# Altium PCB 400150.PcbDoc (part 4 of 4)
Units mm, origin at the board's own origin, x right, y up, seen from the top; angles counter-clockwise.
Board outline 101.6 x 63.5 mm, 4 copper layers (Top Layer, Mid-Layer 1, Mid-Layer 2, Bottom Layer), stack 1.582 mm thick; 248 components, 179 nets, 1093 pads, 875 vias.
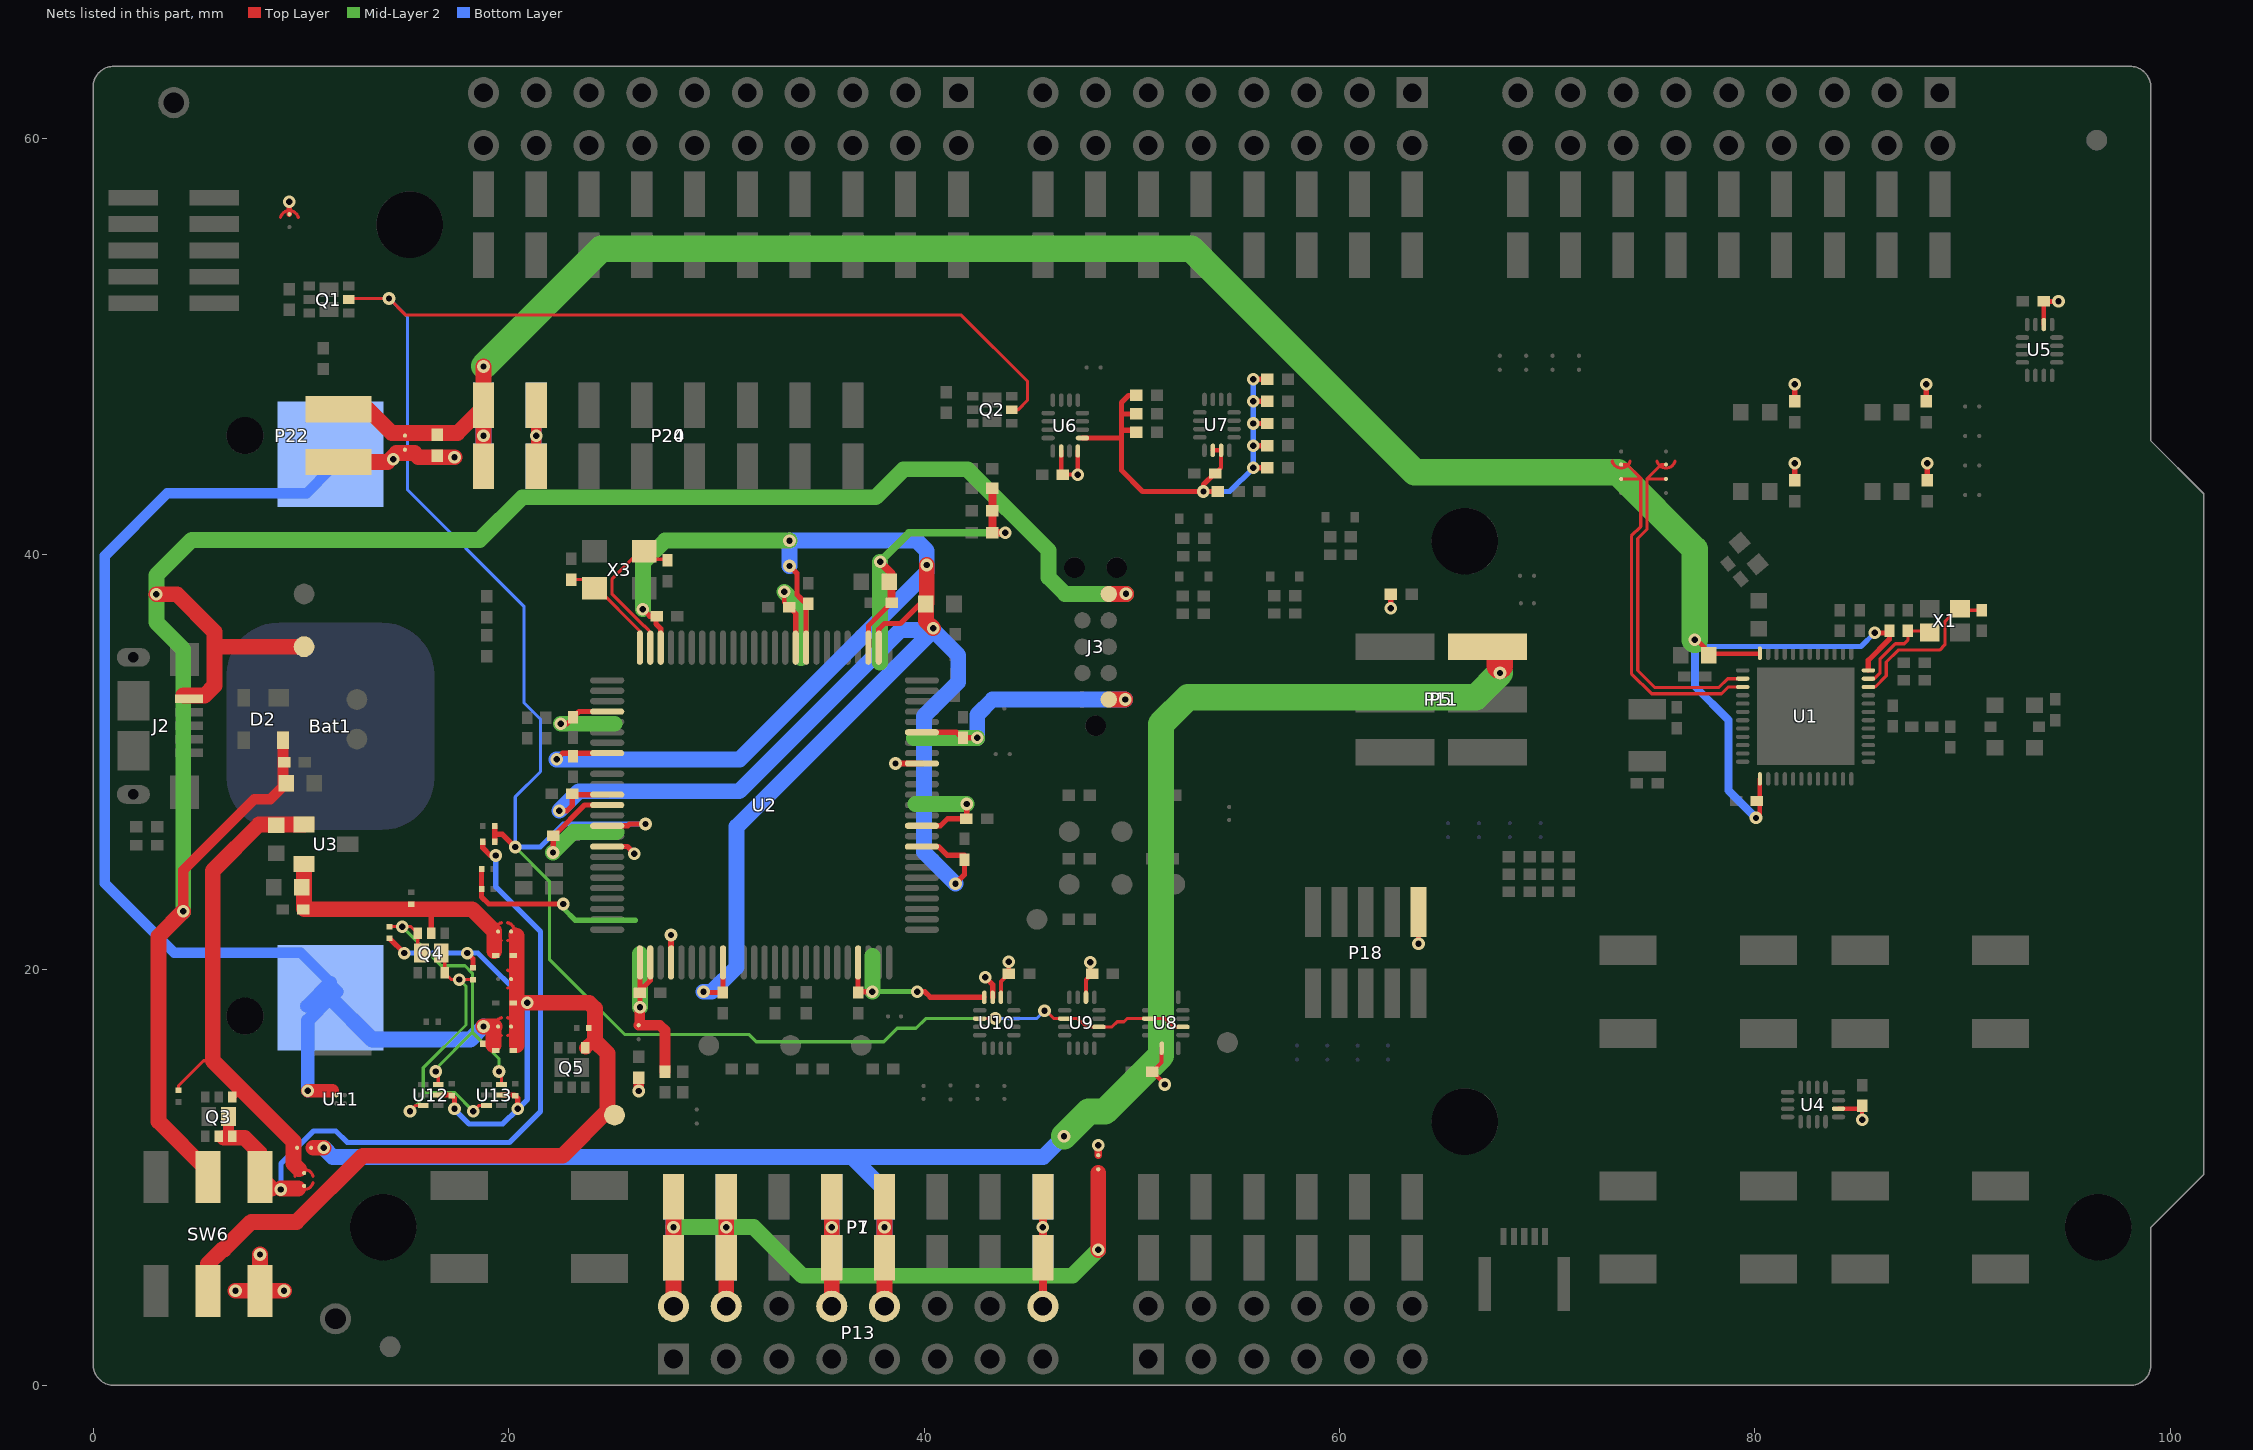
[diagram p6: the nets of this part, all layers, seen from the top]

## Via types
v1: diameter 0.61, hole 0.305, Top Layer to Bottom Layer, tented both sides, 836 vias
v2: diameter 0.61, hole 0.305, Top Layer to Bottom Layer, 23 vias
v3: diameter 0.66, hole 0.33, Top Layer to Bottom Layer, tented both sides, 16 vias

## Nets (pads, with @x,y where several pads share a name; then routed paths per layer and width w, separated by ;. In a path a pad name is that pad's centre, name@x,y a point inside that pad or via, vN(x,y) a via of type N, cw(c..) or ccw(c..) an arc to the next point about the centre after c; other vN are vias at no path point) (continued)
USB_DETECT: Q1.2 Q2.2 R44.2 R45.1 U2.90 U8.2 U8.10 U9.2 U9.10 U10.2 | length 117
  Top Layer w0.152: Q1.2@12.299,52.263 12.35,52.314 v1(14.249,52.314) 15.052,51.511 41.798,51.511 44.983,48.326 44.983,47.408 44.53,46.954 Q2.2@44.232,46.954 ; U10.2@42.679,17.65 v1(43.431,17.65) ; v1(45.796,18.034) 45.872,18.034 46.257,17.65 U9.2@46.771,17.65 47.396,17.65 47.796,17.25 U9.10@48.421,17.25 49.051,17.25 49.301,17.501 49.624,17.501 49.773,17.65 U8.10@50.813,17.65 51.616,17.65 52.016,17.25 U8.2@52.463,17.25
  Top Layer w0.254: R44.2@19.335,26.162 19.335,26.518 ; R45.1@19.335,26.924 19.335,26.518 ; v1(20.32,25.908) 19.71,26.518 19.335,26.518 ; U2.90@24.749,26.93 25.733,26.93 25.818,27.015 v1(26.594,27.015)
  Mid-Layer 2 w0.152: v1(20.32,25.908) 21.965,24.263 21.965,20.507 25.58,16.891 31.572,16.891 31.928,16.535 38.063,16.535 38.709,17.181 39.612,17.181 40.081,17.65 v1(43.431,17.65)
  Bottom Layer w0.152: v1(14.249,52.314) 15.137,51.426 15.137,43.104 20.738,37.503 20.738,32.864 21.539,32.063 21.539,29.54 20.32,28.321 v1(20.32,25.908) ; v1(43.431,17.65) 45.412,17.65 v1(45.796,18.034)
  Bottom Layer w0.254: v1(20.32,25.908) 21.524,25.908 22.631,27.015 v1(26.594,27.015)
V5V: P1.5 P5.2 P7.5 P11.2 P13.10 SB34.1 | length 89.5
  Top Layer w0.762: 10.617,11.43 v1(11.1,11.43) ; P13.10@38.1,3.8 P1.5@38.1,6.145 v1(38.1,7.61) P1.5@38.1,9.075 ; P5.2@67.12,35.55 P5.2@67.722,34.947
  Top Layer w1.27: 67.722,34.628 P5.2@67.722,34.947
  Mid-Layer 2 w1.27: v1(46.736,11.984) 47.928,13.176 48.711,13.176 49.505,13.97 51.41,15.875 51.41,31.826 52.705,33.122 66.558,33.122 v1(67.722,34.285)
  Bottom Layer w0.762: v1(11.1,11.43) 11.542,10.988 36.517,10.988 ; P7.5@38.1,6.145 v1(38.1,7.61) 38.1,9.405 36.517,10.988 ; v1(46.736,11.984) 45.74,10.988 36.517,10.988 ; v1(67.722,34.285) P11.2@67.722,35.55
VBAT: Bat1.1 D8.2 R49.1 SB11.2 U11.A1 | length 63.8
  Top Layer w0.254: R49.1@18.751,16.434 19.228,16.434 19.279,16.383 ; v1@18.751,17.227 v1(18.796,17.272)
  Top Layer w0.635: v1(10.338,14.173) 11.532,14.173
  Top Layer w0.762: v1(18.796,17.272) 19.325,17.272 19.279,17.225 19.279,16.383
  Bottom Layer w0.508: Bat1.1@10,20.818 11.428,19.39 Bat1.1@10,20.818 ; Bat1.1@10,20.818 3.912,20.818 0.559,24.171 0.559,39.919 3.581,42.941 Bat1.1@10.279,42.941 ; Bat1.1@10.279,42.941 11.428,44.09 Bat1.1@10.279,42.941
  Bottom Layer w0.635: Bat1.1@10.287,18.249 Bat1.1@11.428,19.39 ; v1(10.338,14.173) 10.338,17.551 Bat1.1@11.43,18.644 ; Bat1.1@11.73,18.943 Bat1.1@11.428,19.245 ; Bat1.1@11.428,19.245 Bat1.1@11.428,19.39 ; Bat1.1@11.428,19.245 Bat1.1@11.428,19.39
  Bottom Layer w0.762: Bat1.1@11.43,18.644 13.437,16.637 18.161,16.637 v1(18.796,17.272)
VBUS: C20.2 C21.2 D2.4 J2.1 J3.5 SW6.5 TP3.1 | length 106.8
  Top Layer w0.508: v1(4.343,22.809) 4.343,24.79 7.762,28.209 8.535,28.209 C20.2@9.297,28.971 ; C20.2@9.144,28.895 D2.4@9.144,31.045
  Top Layer w0.762: v1(3.048,38.075) 4.039,38.075 5.842,36.271 5.842,33.674 5.366,33.198 J2.1@4.343,33.198 ; v1(4.343,22.809) 3.15,21.615 3.15,12.7 5.537,10.312 SW6.5@5.537,10.03 ; 5.878,35.55 TP3.1@10.16,35.55 ; J3.5@48.895,38.09 v1@49.723,38.09
  Mid-Layer 2 w0.762: v1(4.343,22.809) 4.343,35.43 3.048,36.726 v1(3.048,38.075) 3.048,38.989 4.754,40.695 18.618,40.695 20.671,42.748 37.672,42.748 39.018,44.094 42.087,44.094 45.998,40.183 45.998,38.879 46.783,38.093 v1(49.723,38.093)
VBUS': Q3.2 Q3.3 R44.1 SB33.2 SW6.6 | length 35.4
  Top Layer w0.254: R44.1@18.765,26.162 18.765,25.857 19.121,25.502 v1(19.38,25.502)
  Top Layer w0.508: Q3.3@6.52,12.929 6.52,12.159 Q3.3@6.695,11.984
  Top Layer w0.762: 6.299,11.913 7.29,11.913 8.026,11.176 8.026,10.088 SW6.6@7.968,10.03 ; SW6.6@8.037,10.03 SW6.6@8.604,9.463 ; v1@9.042,9.463 9.877,9.463
  Bottom Layer w0.254: v1(9.042,9.423) 9.042,10.668 10.617,12.243 11.684,12.243 12.243,11.684 20.041,11.684 21.539,13.183 21.539,21.844 19.38,24.003 v1(19.38,25.502)
VCORE: C25.2 C27.2 C31.2 C34.2 C36.1 C39.2 C40.2 U2.9 U2.34 U2.52 U2.59 U2.73 U2.83 U2.87 | length 123.2
  Top Layer w0.254: v1(22.317,30.128) 22.608,30.419 U2.83@24.738,30.419 ; v1(22.444,27.65) 22.802,27.65 23.071,27.919 C40.2@23.071,28.489 ; C40.2@23.24,28.43 U2.87@24.749,28.43 ; v1(26.467,37.353) 26.797,37.023 C36.1@27.101,37.023 ; C36.1@27.125,37.023 C36.1@27.101,37.023 ; U2.73@27.324,35.505 27.324,36.42 27.101,36.643 C36.1@27.101,37.023 ; v1(29.388,18.938) 29.421,18.905 C25.2@30.318,18.905 ; C25.2@30.324,18.93 U2.9@30.324,20.355 ; v1(33.528,39.436) 33.807,39.157 33.884,39.08 33.884,38.055 34.036,37.903 C34.2@34.378,37.561 ; U2.59@34.324,35.505 34.324,37.507 C34.2@34.378,37.561 ; C34.2@34.432,37.615 C34.2@34.378,37.561 ; U2.52@37.824,35.505 37.824,36.391 38.101,36.667 38.862,36.667 39.802,37.607 C31.2@40.092,37.607 ; U2.34@39.899,25.93 40.7,25.93 41.113,25.517 C27.2@41.908,25.517 ; v1(41.519,24.145) 41.951,24.577 C27.2@41.951,25.296 ; C27.2@41.933,25.356 C27.2@41.933,25.517
  Top Layer w0.762: v1(40.132,39.487) 40.132,37.647 C31.2@40.092,37.607 40.092,36.784 v1(40.437,36.439)
  Mid-Layer 2 w0.762: v1(26.467,37.353) 26.467,39.588 27.534,40.655 v1(33.528,40.655)
  Bottom Layer w0.762: v1(22.317,30.128) 31.128,30.128 40.132,39.131 v1(40.132,39.487) 40.132,40.173 39.649,40.655 v1(33.528,40.655) v1(33.528,39.436) ; v1(22.444,27.65) 23.383,28.59 31.105,28.59 38.862,36.347 v1@40.437,36.347 ; v1(29.388,18.938) 29.784,18.938 30.978,20.132 30.978,26.888 v1@40.437,36.347 ; v1(41.519,24.145) 39.995,25.669 39.995,32.201 41.646,33.852 41.646,35.138 v1@40.437,36.347
VDD: C14.2 C44.2 C45.2 C46.2 C54.2 C55.2 P18.1 P20.2 P22.2 P24.2 R1.2 R2.2 R3.2 R4.2 R6.1 R39.2 R57.2 SB9.2 SB32.1 SB35.2 SW6.3 U4.14 U5.14 U6.14 U6.16 U8.14 U9.14 U10.14 U10.15 | length 36.8
  Top Layer w0.203: U10.14@43.704,18.675 43.704,19.439 C55.2@44.077,19.812 v1(44.077,20.388) ; C46.2@46.526,43.951 46.638,43.839 C46.2@46.642,43.835 ; C46.2@46.603,43.917 U6.14@46.603,44.972 ; C46.2@46.685,43.835 v1(47.396,43.835) ; v1@47.403,43.835 U6.16@47.403,44.972 ; U9.14@47.796,18.675 47.796,19.518 C54.2@48.09,19.812 48.006,19.896 v1(48.006,20.359) ; U8.14@51.438,16.225 51.438,15.531 C14.2@50.995,15.088 51.587,14.495 v1(51.587,14.478) ; U4.14@84.02,13.313 85.153,13.313 C44.2@85.158,13.318 ; v1(85.158,12.776) C44.2@85.158,13.318 ; C44.2@85.158,13.445 C44.2@85.158,13.318 ; C45.2@93.896,52.172 93.901,52.167 U5.14@93.901,51.06
  Top Layer w0.254: SB32.1@9.449,56.37 9.449,56.545 v1(9.449,56.972) ; v1(42.951,19.634) 43.304,19.282 U10.15@43.304,18.675 ; v1(62.467,37.397) R39.2@62.467,38.075 ; v1(63.805,21.26) P18.1@63.805,22.772 ; R3.2@81.915,43.553 v1(81.915,44.374) ; R1.2@81.915,47.363 v1(81.915,48.192) ; R2.2@88.24,47.363 v1(88.24,48.184) ; R4.2@88.291,43.553 v1(88.291,44.374) ; C45.2@93.896,52.172 v1(94.607,52.172)
  Top Layer w0.381: SB35.2@48.387,11.072 v1(48.387,11.557)
  Top Layer w0.508: P20.2@21.336,44.245 v1(21.336,45.71) P20.2@21.336,47.175 ; v1(26.266,14.165) R57.2@26.266,14.806
  Top Layer w0.762: v1(6.858,4.548) v1(9.195,4.548) ; SW6.3@8.037,4.479 v1(8.037,6.29) ; P22.2@11.811,44.44 14.173,44.44 14.605,44.872 15.469,44.872 15.672,44.668 v1(17.399,44.668)
  Bottom Layer w0.508: P24.2@21.336,44.245 v1(21.336,45.71) P24.2@21.336,47.175
  other v1: 14.453,44.567
VDD_NRF: C5.1 C8.1 C9.1 P20.1 P22.1 P24.1 R6.2 SB9.1 U1.13 U1.36 U1.48 | length 114
  Top Layer w0.229: v1(77.105,35.888) 77.188,35.888 77.78,35.296 77.865,35.211 U1.48@80.225,35.211 ; v1(80.047,27.309) 80.235,27.497 U1.13@80.235,29.186
  Top Layer w0.254: U1.36@85.457,34.439 85.457,34.899 86.473,35.915 C8.1@86.473,36.207 ; v1(85.762,36.225) 85.779,36.207 C8.1@86.473,36.207 ; C8.1@86.473,36.309 C8.1@86.473,36.207
  Top Layer w0.381: C9.1@77.78,35.126 C9.1@77.78,35.296
  Top Layer w0.762: P22.1@11.811,46.98 13.233,46.98 14.376,45.837 17.547,45.837 18.796,47.086 v1(18.796,45.71) P20.1@18.796,44.245 ; P20.1@18.796,47.175 v1(18.796,49.037)
  Mid-Layer 2 w1.27: v1@18.821,49.063 24.47,54.712 52.857,54.712 63.627,43.942 73.406,43.942 77.105,40.243 v1(77.105,35.888)
  Bottom Layer w0.254: v1(77.105,35.888) 77.429,35.564 85.101,35.564 v1(85.762,36.225)
  Bottom Layer w0.381: v1(77.105,35.888) 77.105,33.65 78.728,32.027 78.728,28.629 v1(80.047,27.309)
  Bottom Layer w0.762: P24.1@18.796,44.245 v1(18.796,45.71) P24.1@18.796,47.175
VDD_SAM: C24.2 C26.2 C28.2 C29.2 C32.2 C33.2 C35.2 C38.2 C41.2 J3.1 R5.2 R19.2 R20.2 R21.2 R22.2 R23.2 SB29.2 U2.1 U2.2 U2.4 U2.22 U2.36 U2.42 U2.45 U2.53 U2.60 U2.79 U2.88 U2.92 U10.16 | length 91.5
  Top Layer w0.152: U2.88@24.749,27.93 U2.88@24.917,27.93
  Top Layer w0.203: v1(33.274,38.2) 33.274,37.691 C35.2@33.51,37.455
  Top Layer w0.254: R20.2@18.704,24.844 R19.2@18.704,23.893 18.704,23.511 19.05,23.165 v1(22.631,23.165) ; v1@22.147,25.644 C41.2@22.147,26.457 ; C41.2@22.223,26.49 23.663,27.93 U2.88@24.749,27.93 ; v1(22.52,31.841) 22.807,31.841 C38.2@23.104,32.138 ; C38.2@23.112,32.146 23.396,32.43 U2.79@24.749,32.43 ; U2.92@24.749,25.93 25.721,25.93 v1(26.059,25.592) ; U2.1@26.324,20.355 26.324,18.887 26.326,18.886 v1(26.326,18.196) ; C24.2@26.33,18.989 26.824,19.483 U2.2@26.824,20.355 ; C35.2@33.51,37.455 33.824,37.141 U2.60@33.824,35.505 ; C26.2@36.824,19.104 U2.22@36.824,20.355 ; C26.2@36.863,18.938 v1(37.516,18.938) ; U2.53@37.324,35.505 37.324,36.562 37.587,36.825 38.333,37.571 C32.2@38.333,37.658 ; v1(39.675,18.948) 40.03,18.948 40.304,18.675 U10.16@42.875,18.675 ; U2.36@39.899,26.93 40.798,26.93 41.138,27.269 C28.2@42.035,27.269 42.052,27.287 v1(42.052,27.981) ; U2.42@39.899,29.93 U2.42@39.918,29.911 ; U2.45@39.899,31.43 41.55,31.43 C29.2@41.74,31.24 ; C29.2@41.875,31.164 v1(42.56,31.164)
  Top Layer w0.305: U2.4@27.824,20.355 v1(27.824,21.676) ; v1(38.629,29.93) U2.42@39.899,29.93
  Top Layer w0.381: v1(37.887,39.639) 38.438,39.088 C32.2@38.438,37.658 ; R23.2@43.295,43.17 R22.2@43.295,42.103 R21.2@43.295,41.036 v1(43.906,41.036)
  Top Layer w0.508: v1(26.326,18.196) 26.326,17.39 SB29.2@26.266,17.33 27.287,17.33 27.532,17.085 R5.2@27.532,15.101
  Top Layer w0.762: J3.1@48.895,33.01 v1(49.682,33.01)
  Mid-Layer 2 w0.254: v1(22.631,23.165) 22.631,22.963 23.217,22.377 26.111,22.377 ; v1@37.526,18.948 v1(39.675,18.948)
  Mid-Layer 2 w0.381: v1(37.887,39.639) 39.284,41.036 v1(43.906,41.036)
  Mid-Layer 2 w0.508: v1(37.516,18.938) v1@37.526,18.948
  Mid-Layer 2 w0.762: v1(22.139,25.644) 23.123,26.628 25.193,26.628 ; v1(22.52,31.841) 25.116,31.841 ; v1(26.326,18.196) 26.326,20.76 ; v1(33.274,38.2) 34.083,37.391 34.083,35.01 ; v1(37.516,18.938) 37.516,20.659 ; 37.887,34.781 v1(37.887,39.639) ; 39.518,31.164 v1(42.56,31.164) ; 39.594,27.981 v1(42.052,27.981)
  Bottom Layer w0.762: v1(42.56,31.164) 42.56,32.273 43.297,33.01 v1(49.682,33.01)
VEXT: C47.2 R29.2 R30.2 R31.2 R32.2 R33.2 R34.2 R35.2 R36.2 R37.2 U6.1 U7.14 U7.15 | length 25.8
  Top Layer w0.203: U7.14@53.9,45.003 U7.15@54.3,45.003 54.3,44.168 C47.2@54.018,43.885
  Top Layer w0.254: U6.1@47.628,45.597 49.503,45.597 ; R29.2@50.214,45.867 50.113,45.968 49.581,45.968 49.503,46.046 ; R30.2@50.214,46.756 49.503,46.756 ; R31.2@50.214,47.645 49.839,47.645 49.503,47.308 49.503,46.756 ; C47.2@54,43.903 53.449,43.352 v1(53.449,43.022) ; R37.2@54.143,43.022 v1(53.449,43.022) ; v1(55.853,44.161) R32.2@56.521,44.161 ; v1(55.853,45.228) R33.2@56.521,45.228 ; v1(55.853,46.295) R34.2@56.521,46.295 ; v1(55.853,47.361) R35.2@56.521,47.361 ; v1(55.853,48.428) R36.2@56.521,48.428 ; 49.503,45.597 49.503,46.046 ; 49.503,45.597 49.503,44.044 50.525,43.022 v1(53.449,43.022) ; 49.503,46.046 49.503,46.756
  Bottom Layer w0.254: v1(53.449,43.022) 54.714,43.022 v1(55.853,44.161) v1(55.853,45.228) v1(55.853,46.295) v1(55.853,47.361) v1(55.853,48.428)
VEXT_DETECT: Q4.3 R47.2 U12.6 U13.6 | length 16.1
  Top Layer w0.152: R47.2@14.275,22.078 v1(14.884,22.078) 15.306,22.078 Q4.3@15.631,21.753 ; Q4.3@15.631,21.748 15.631,20.978 Q4.3@15.806,20.803 ; v1(16.492,15.105) 16.619,14.978 U12.6@16.619,14.47 ; v1(19.54,15.105) 19.667,14.978 U13.6@19.667,14.47
  Mid-Layer 2 w0.152: v1(14.884,22.078) 16.77,20.193 17.907,20.193 18.263,19.837 18.263,16.993 ; v1(16.492,15.105) 16.492,15.222 18.263,16.993 ; v1(19.54,15.105) 19.54,15.716 18.263,16.993
VIN: P1.8 P7.8 P13.16 | length 8.2
  Top Layer w0.381: P13.16@45.72,3.8 P1.8@45.72,6.145 v1(45.72,7.61) P1.8@45.72,9.075
  Bottom Layer w0.381: P7.8@45.72,6.145 v1(45.72,7.61) P7.8@45.72,9.075
VIO: P1.1 P1.2 P1.4 P7.1 P7.2 P7.4 P13.2 P13.4 P13.8 SB35.1 | length 54
  Top Layer w0.381: v1(35.56,7.61) P1.4@35.56,9.075
  Top Layer w0.762: P13.2@27.94,3.8 P1.1@27.94,6.145 P1.1@27.94,9.075 ; P13.4@30.48,3.8 v1(30.48,7.61) P1.2@30.48,9.075 ; P13.8@35.56,3.8 P1.4@35.56,9.075 ; v1(48.387,6.518) 48.387,10.226
  Mid-Layer 2 w0.762: v1(27.94,7.61) v1(30.48,7.61) 31.801,7.61 34.138,5.273 35.535,5.273 47.142,5.273 v1(48.387,6.518) ; 35.56,5.298 v1(35.56,7.61)
  Bottom Layer w0.762: P7.1@27.94,6.145 P7.1@27.94,9.075 ; P7.2@30.48,6.145 P7.2@30.48,9.075 ; P7.4@35.56,6.145 P7.4@35.56,9.075
VREG_DETECT: Q4.6 R46.2 U12.3 U13.3 | length 14.4
  Top Layer w0.152: v1(15.258,13.191) 15.538,13.47 U12.3@15.893,13.47 ; Q4.6@16.756,20.803 16.931,20.628 Q4.6@16.931,19.858 ; Q4.6@16.931,19.853 17.257,19.527 v1(17.628,19.527) R46.2@18.288,19.527 ; v1(18.306,13.191) 18.586,13.47 U13.3@18.941,13.47
  Mid-Layer 2 w0.152: v1(15.258,13.191) 15.893,13.826 15.893,14.097 ; v1(17.628,19.527) 17.952,19.202 17.952,17.342 15.893,15.283 15.893,14.097 ; v1(18.306,13.191) 17.4,14.097 15.893,14.097
VREG_IN: C16.2 Q3.4 R60.1 SB33.1 SB34.2 U3.1 | length 29.6
  Top Layer w0.152: R60.1@4.115,14.204 4.115,14.419 5.317,15.621 5.766,15.621
  Top Layer w0.381: Q3.4@6.695,13.874 7.087,14.265 7.087,14.3
  Top Layer w0.762: 5.842,24.846 7.986,26.99 ; 9.917,10.397 9.643,10.672 9.643,11.744 7.087,14.3 5.766,15.621 5.766,24.769 7.986,26.99 ; 7.986,26.99 U3.1@10.16,26.99 7.986,26.99
VREG_OUT: C17.2 C18.2 D1.2 Q4.2 R50.1 SB10.2 U3.2 | length 13.9
  Top Layer w0.254: Q4.2@16.281,21.753 16.281,22.901
  Top Layer w0.762: U3.2@10.16,25.09 10.16,22.934 10.178,22.916 16.266,22.916 ; 16.281,22.901 16.266,22.916 ; 19.312,20.891 19.312,21.861 18.257,22.916 16.266,22.916
VSUPPLY: C56.2 C57.2 D1.1 D7.1 D8.1 Q5.4 R46.1 R47.1 R48.1 SB10.1 SB11.1 SB12.1 SW6.2 TP14.1 U12.5 U13.5 | length 58.9
  Top Layer w0.254: R47.1@14.275,21.508 v1(14.98,20.803) ; U12.5@16.619,13.97 17.241,13.97 C56.2@17.272,13.939 17.399,13.812 v1(17.399,13.304) ; v1(18.009,20.803) 18.288,20.523 R46.1@18.288,20.097 ; U13.5@19.667,13.97 20.289,13.97 C57.2@20.32,13.939 20.447,13.812 v1(20.447,13.304)
  Top Layer w0.635: 20.32,21.641 20.32,21.717 ; D7.1@20.396,18.415 v1@20.676,18.415 ; Q5.4@23.718,16.236 24.071,16.589
  Top Layer w0.762: SW6.2@5.537,4.53 5.537,5.842 6.236,6.541 6.297,6.541 7.62,7.864 9.794,7.864 12.979,11.049 22.606,11.049 24.765,13.208 24.765,15.977 24.155,16.586 24.155,18.136 23.876,18.415 v1(20.904,18.415) v1@20.676,18.415 ; 20.396,16.383 20.396,18.415 20.396,21.641
  Bottom Layer w0.254: v1(14.98,20.803) v1(18.009,20.803) 18.517,20.803 v1(20.904,18.415) 20.904,13.761 v1(20.447,13.304) 19.716,12.573 18.098,12.573 v1@17.399,13.272
XC1: C1.1 U1.34 X1.1 | length 8
  Top Layer w0.152: U1.34@85.46,33.611 85.784,33.611 86.318,34.146 86.318,34.814 86.89,35.386 88.886,35.386 89.14,35.64 89.14,36.758 89.691,37.309 C1.1@90.918,37.309
XC2: C2.1 U1.35 X1.3 | length 4.7
  Top Layer w0.152: U1.35@85.46,34.011 85.75,34.011 86.013,34.275 86.013,34.944 86.761,35.691 87.185,35.691 87.362,35.869 C2.1@87.362,36.301 ; C2.1@87.311,36.309 88.268,36.309 X1.3@88.468,36.109
XIN: C22.1 U2.75 X3.3 | length 5.1
  Top Layer w0.152: C22.1@23.028,38.784 23.732,38.784 X3.3@24.145,38.371 ; X3.3@24.145,38.368 24.264,38.368 26.324,36.308 U2.75@26.324,35.505
XL1: SB2.2 SB4.1 U1.2 | length 17.1
  Top Layer w0.152: SB2.2@75.717,43.627 74.813,43.627 74.803,43.637 ; SB4.1@75.717,44.323 75.489,44.323 74.803,43.637 ; U1.2@79.41,34.011 78.683,34.011 78.26,33.588 75.175,33.588 74.358,34.405 74.358,40.759 74.803,41.204 74.803,43.637
XL2: SB1.2 SB3.1 U1.3 | length 17.6
  Top Layer w0.152: SB1.2@73.558,43.627 74.463,43.627 ; SB3.1@73.558,44.323 73.838,44.323 74.498,43.663 74.498,41.331 74.053,40.885 74.053,34.253 75.022,33.283 78.386,33.283 78.714,33.611 U1.3@79.41,33.611
XOUT: C23.1 U2.74 X3.1 | length 7.5
  Top Layer w0.152: U2.74@26.824,35.505 26.824,36.259 26.67,36.413 26.525,36.558 26.505,36.558 24.984,38.079 24.984,38.816 26.316,40.149 X3.1@26.533,40.149 26.924,39.758 C23.1@27.651,39.758
pads on no net: Bat1.0 Fid1.0 Fid2.0 J2.4 J2.6@1.944,28.44 J2.6@1.944,35.04 J3.0 J3.7 J3.9 P18.7 P18.8 P19.7 P19.8 P21.0 P22.0 P23.0 P23.1 P23.3 P23.5 SW6.1 SW6.4 U1.44 U2.6 U2.8 U2.10 U2.11 U2.13 U2.15 U2.16 U2.19 U2.25 U2.26 U2.28 U2.29 U2.30 U2.31 U2.32 U2.33 U2.37 U2.44 U2.48 U2.49 U2.50 U2.58 U2.64 U2.69 U2.86 U2.93 U2.94 U2.95 U2.96 U2.99 U2.100 U4.10 U5.10 U6.3 U6.7 U6.10 U6.11 U6.15 U8.1 U8.5 U8.9 U8.13 U9.1 U9.5 U9.9 U9.13 U10.1 U10.10 U10.11 U10.12 U10.13

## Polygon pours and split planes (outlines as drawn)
VDD on Mid-Layer 2 "Mid_Layer_2-VDD" (solid, remove dead copper, pour order 19): 0,1.006 0,62.499 cw(c1.003,62.487) 1.016,63.49 98.044,63.49 cw(c98.044,62.474) 99.06,62.474 99.06,45.456 101.6,42.916 101.6,10.15 99.06,7.61 99.06,1.006 cw(c98.057,0.993) 98.069,-0.01 1.016,-0.01 cw(c1.016,1.006)
VDD_SAM on Mid-Layer 2 "NONET_L03_P008" (solid, pour order 12): 24.435,35.772 24.435,20.03 40.153,20.03 40.153,35.772
GND on Mid-Layer 1 "Mid_Layer_1-GND" (solid, remove dead copper, pour order 10): 0,1.006 0,62.499 cw(c1.003,62.487) 1.016,63.49 98.044,63.49 cw(c98.044,62.474) 99.06,62.474 99.06,45.456 101.6,42.916 101.6,10.15 99.06,7.61 99.06,1.006 cw(c98.057,0.993) 98.069,-0.01 1.016,-0.01 cw(c1.016,1.006)
GND on Top Layer "Top_Layer-GND" (solid, remove dead copper, pour order 18): 0,1.006 0,62.499 cw(c1.003,62.487) 1.016,63.49 98.044,63.49 cw(c98.044,62.474) 99.06,62.474 99.06,45.456 101.6,42.916 101.6,10.15 99.06,7.61 99.06,1.006 cw(c98.057,0.993) 98.069,-0.01 1.016,-0.01 cw(c1.016,1.006)
GND on Bottom Layer "Bottom_Layer-GND" (solid, remove dead copper, pour order 7): 0,1.006 0,62.499 cw(c1.003,62.487) 1.016,63.49 98.044,63.49 cw(c98.044,62.474) 99.06,62.474 99.06,45.456 101.6,42.916 101.6,10.15 99.06,7.61 99.06,1.006 cw(c98.057,0.993) 98.069,-0.01 1.016,-0.01 cw(c1.016,1.006)

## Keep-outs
Keep-Out Layer:
  circle w0.152: c66.04,12.69 r2.4
  circle w0.152: c15.24,55.87 r2.4
  circle w0.152: c66.04,40.63 r2.4
  circle w0.152: c96.52,7.61 r2.4
  circle w0.152: c13.97,7.61 r2.4
  lines w0.254: 98.069,-0.01 ccw(c98.057,0.993) 99.06,1.006 99.06,7.61 101.6,10.15 101.6,42.916 99.06,45.456 99.06,62.474 ccw(c98.044,62.474) 98.044,63.49 1.016,63.49 ccw(c1.003,62.487) 0,62.499 0,1.006 ccw(c1.016,1.006) 1.016,-0.01 98.095,-0.01
Mechanical 2:
  lines w0.025: 5.309,33.872 7.442,33.872 ; 5.512,30.698 10.455,30.698 10.891,30.262 13.397,30.262 ccw(c13.397,31.366) 14.177,30.586 17.872,34.28 cw(c18.833,33.319) 18.833,34.678 19.421,34.678 ; 9.906,33.872 11.863,33.872 ccw(c11.863,34.457) 12.276,34.044 16.125,37.893 cw(c17.44,36.578) 17.44,38.437 ; 17.44,38.445 23.561,38.445 cw(c23.561,37.219) 24.428,38.086 26.916,35.599 ; 19.408,34.678 cw(c19.408,33.451) 20.276,34.319 22.763,31.831 ; 25.344,31.804 ccw(c25.344,34.027) 26.916,35.599

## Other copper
Top Layer:
  rectangle net ANT: 100,13.655 101.27,14.417
  pour cut-out: 9.86,34.145 11.774,34.145 ccw(c11.774,34.466) 12.001,34.239 13.311,35.55 14.287,35.55 14.287,30.404 cw(c13.296,31.425) 13.274,30.002 11.169,30.002 cw(c11.169,30.93) 10.513,30.274 ccw(c10.035,29.798) 10.034,30.472 5.422,30.472 5.422,34.148 7.355,34.148 7.411,34.138 7.465,34.12 7.51,34.094 7.553,34.059 7.584,34.013 7.602,33.97 7.607,33.924 7.607,33.877 7.607,32.675 9.354,32.675 9.354,33.64 cw(c9.86,33.64)
  pour cut-out: 15.839,38.081 cw(c17.348,36.573) 17.348,38.706 21.082,38.706 21.082,34.455 18.606,34.45 ccw(c18.779,33.396) 17.954,34.074 16.815,32.935 15.839,32.935
  pour cut-out: 18.252,38.709 23.149,38.71 cw(c23.15,36.174) 24.945,37.966 27.079,35.832 cw(c25.288,34.038) 27.823,34.035 27.823,33.767 cw(c25.613,33.767) 25.613,31.557 23.404,31.557 cw(c23.403,33.169) 22.263,32.029 20.149,34.143 ccw(c19.38,33.376) 19.378,34.463 18.241,34.463 cw(c129.357,36.292)
  pour cut-out: 60.528,30.927 68.073,30.927 68.071,32.705 60.528,32.705
  pour cut-out: 9.449,33.492 11.684,33.492 11.684,31.791 9.449,31.791
  pour cut-out: 8.687,18.557 10.922,18.557 10.922,14.239 8.687,14.239
  pour cut-out: -0.229,28.194 2.824,28.194 2.818,35.27 -0.228,35.27
  pour cut-out: 88.15,30.611 85.407,30.611 85.407,33.507 88.15,33.507
  pour cut-out: 57.506,40.665 59.093,42.253 59.093,40.589 58.572,40.069 58.572,39.182 57.506,39.182
  pour cut-out: 13.311,35.55 15.839,38.077 15.839,38.081 17.291,38.081 17.526,37.846 16.815,37.135 16.815,32.935 14.287,30.407 14.287,30.404 13.538,30.404 13.208,30.734 13.208,34.798
Mid-Layer 1:
  pour cut-out: 76.487,45.325 72.943,45.325 72.943,42.578 76.487,42.578
  pour cut-out: 44.485,33.537 43.247,33.537 43.247,32.216 44.485,32.216
  pour cut-out: 44.414,31.116 43.176,31.116 43.176,29.795 44.414,29.795
  pour cut-out: 39.193,18.396 37.955,18.396 37.955,17.075 39.193,17.075
  pour cut-out: 26.878,17.601 25.64,17.601 25.64,16.281 26.878,16.281
  pour cut-out: 20.454,22.495 19.216,22.495 19.216,21.174 20.454,21.174
  pour cut-out: 20.454,20.212 19.216,20.212 19.216,18.891 20.454,18.891
  pour cut-out: 20.454,17.929 19.216,17.929 19.216,16.608 20.454,16.608
  pour cut-out: 10.078,55.455 8.84,55.455 8.84,56.775 10.078,56.775
  pour cut-out: 15.632,44.738 14.393,44.738 14.393,46.059 15.632,46.059
  pour cut-out: 48.781,48.396 47.542,48.396 47.542,49.717 48.781,49.717
  pour cut-out: 69.658,37.067 68.42,37.067 68.42,39.683 69.658,39.683
  pour cut-out: 67.029,48.607 67.029,49.845 72.247,49.845 72.247,48.607
  pour cut-out: 89.839,47.741 91.077,47.741 91.077,42.129 89.839,42.129
  pour cut-out: 47.77,11.327 49.008,11.327 49.008,10.006 47.77,10.006
  pour cut-out: 39.374,14.7 44.475,14.7 44.475,13.513 39.374,13.513
  pour cut-out: 28.432,13.564 29.67,13.564 29.67,12.243 28.432,12.243
  pour cut-out: 95.069,30.052 86.027,30.052 86.027,33.354 95.069,33.354
Mid-Layer 2:
  pour cut-out: 64.466,27.44 70.41,27.44 70.41,26.002 64.466,26.002
  pour cut-out: 57.125,16.755 63.068,16.755 63.068,15.316 57.125,15.316
  pour cut-out: 25.167,20.125 25.167,17.839 25.929,17.839 25.929,20.125
  pour cut-out: 95.069,30.052 86.027,30.052 86.027,33.354 95.069,33.354
Multi-Layer:
  pour cut-out: 94.995,-0.01 101.86,-0.01 101.823,45.405 95,45.405

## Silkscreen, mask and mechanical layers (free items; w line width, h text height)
Top Overlay:
  drawing of 76 lines, arcs and shapes, not listed
  text "GND" at 10.668,61.712 h1.78
  text "GND" at 94.158,61.661 h1.78
  text "GND" at 2.464,59.172 h1.78
  text "0111GETR" at 97.815,52.527 h1.52 r90
  text "400150" at 96.512,52.462 h2.03 r90
  text "P0.27" at 19.304,49.875 h1.78 r90
  text "P0.26" at 21.844,49.875 h1.78 r90
  text "P0.02" at 24.384,49.875 h1.78 r90
  text "GND" at 26.924,49.875 h1.78 r90
  text "P0.25" at 29.464,49.875 h1.78 r90
  text "P0.24" at 32.004,49.875 h1.78 r90
  text "P0.23" at 34.544,49.875 h1.78 r90
  text "P0.22" at 37.084,49.875 h1.78 r90
  text "P0.20" at 39.624,49.875 h1.78 r90
  text "P0.19" at 42.164,49.875 h1.78 r90
  text "P0.18" at 46.228,49.875 h1.78 r90
  text "P0.17" at 48.768,49.875 h1.78 r90
  text "P0.16" at 51.308,49.875 h1.78 r90
  text "P0.15" at 53.848,49.875 h1.78 r90
  text "P0.14" at 56.388,49.875 h1.78 r90
  text "P0.13" at 58.928,49.875 h1.78 r90
  text "P0.12" at 61.468,49.875 h1.78 r90
  text "P0.10" at 69.088,49.875 h1.78 r90
  text "P0.09" at 71.628,49.875 h1.78 r90
  text "P0.08" at 74.168,49.875 h1.78 r90
  text "P0.07" at 76.708,49.875 h1.78 r90
  text "P0.06" at 79.248,49.875 h1.78 r90
  text "P0.05" at 81.788,49.875 h1.78 r90
  text "P0.21" at 84.328,49.875 h1.78 r90
  text "P0.01" at 86.868,49.875 h1.78 r90
  text "P0.00" at 89.433,49.875 h1.78 r90
  text "Debug out" at 0.406,49.748 h2.03
  text "LED1" at 77.724,47.549 h2.03
  text "LED2" at 84.049,47.549 h2.03
  text "GPIO" at 70.002,44.069 h1.52
  text "LED3" at 77.724,43.764 h2.03
  text "LED4" at 84.049,43.764 h2.03
  text "XTAL" at 70.002,42.799 h1.52
  text "nRF current" at 3.632,41.62 h2.03
  text "VTG" at 24.308,41.046 h1.4 r90
  text "VDD / nRF" at 19.761,40.97 h1.4 r90
  text "VDD" at 21.768,40.982 h1.4 r90
  text "(ARDUINO D0) P0.11" at 64.033,40.843 h1.78 r90
  text "SWD / IO" at 27.508,40.742 h1.4 r90
  text "SWD / CLK" at 30.048,40.742 h1.4 r90
  text "SWO" at 31.928,40.73 h1.4 r90
  text "measurement" at 3.15,40.325 h2.03
  text "RESET" at 34.519,39.801 h1.4 r90
  text "GND / DETECT" at 38.252,39.614 h1.4 r90
  text "P0.24" at 57.767,35.072 h1.52
  text "5V" at 69.248,35.021 h1.52
  text "P0.23" at 69.248,32.557 h1.52
  text "P0.25" at 57.717,32.532 h1.52
  text "DETECT" at 69.16,30.063 h1.52
  text "RESET" at 56.955,29.992 h1.52
  text "Button 1" at 74.191,22.287 h2.29
  text "Button 2" at 85.163,22.287 h2.29
  text "External supply" at 2.311,20.691 h2.03
  text "-" at 13.767,18.252 h1.78
  text "Debug in" at 58.191,16.002 h2.03
  text "+" at 13.767,15.712 h1.78
  text "Button 4" at 85.214,11.097 h2.29
  text "Button 3" at 74.114,11.086 h2.29
  text "N.C." at 46.253,10.455 h1.78 r90
  text "VDD" at 28.365,10.451 h1.78 r90
  text "VDD" at 30.905,10.451 h1.78 r90
  text "RESET" at 33.445,10.451 h1.78 r90
  text "VDD" at 35.985,10.451 h1.78 r90
  text "5V" at 38.525,10.451 h1.78 r90
  text "GND" at 41.065,10.451 h1.78 r90
  text "GND" at 43.605,10.451 h1.78 r90
  text "P0.03" at 51.225,10.451 h1.78 r90
  text "P0.04" at 53.765,10.451 h1.78 r90
  text "P0.28" at 56.305,10.451 h1.78 r90
  text "P0.29" at 58.845,10.451 h1.78 r90
  text "P0.30" at 61.385,10.451 h1.78 r90
  text "P0.31" at 63.925,10.451 h1.78 r90
  text "NFC" at 67.513,7.899 h2.29
  text "GND" at 10.382,4.406 h1.78
  text "IF BOOT/RESET" at 15.215,2.972 h2.03
  text "OFF" at 2.921,1.869 h1.78
  text "ON" at 6.35,1.869 h1.78
  text "nRF52-DK" at 89.219,1.856 h2.54
  text "GND" at 19.812,0.752 h1.78
  text "Power" at 3.353,0.498 h2.03
Bottom Overlay:
  drawing of 11657 lines, arcs and shapes, not listed
  text "J-Link" at 9.242,60.965 h1.45 r90
  text "www.segger.com" at 10.393,60.884 h1.68 r90
  text "TM" at 8.821,57.495 h0.94 r90
  text "S" at 7.383,57.282 h1.35 r90
  text "E" at 7.383,56.392 h1.35 r90
  text "Technology" at 9.242,56.213 h1.45 r90
  text "G" at 7.383,55.608 h1.35 r90
  text "Pb" at 96.705,54.752 h3.05 r90
  text "G" at 7.383,54.618 h1.35 r90
  text "E" at 7.383,53.594 h1.35 r90
  text "P0.27 (SCL)" at 19.304,53.101 h1.02 r90
  text "P0.26 (SDA)" at 21.844,53.101 h1.02 r90
  text "P0.02 (AREF)" at 24.384,53.101 h1.02 r90
  text "GND" at 26.924,53.101 h1.02 r90
  text "P0.25 (D13)" at 29.464,53.101 h1.02 r90
  text "P0.24 (D12)" at 32.004,53.101 h1.02 r90
  text "P0.23 (D11)" at 34.544,53.101 h1.02 r90
  text "P0.22 (D10)" at 37.084,53.101 h1.02 r90
  text "P0.20 (D9)" at 39.624,53.101 h1.02 r90
  text "P0.19 (D8)" at 42.164,53.101 h1.02 r90
  text "P0.18 (D7)" at 46.228,53.101 h1.02 r90
  text "P0.17 (D6)" at 48.768,53.101 h1.02 r90
  text "P0.16 (D5)" at 51.308,53.101 h1.02 r90
  text "P0.15 (D4)" at 53.848,53.101 h1.02 r90
  text "P0.14 (D3)" at 56.388,53.101 h1.02 r90
  text "P0.13 (D2)" at 58.928,53.101 h1.02 r90
  text "P0.12 (D1)" at 61.468,53.101 h1.02 r90
  text "P0.11 (ARDUINO D0)" at 64.008,53.101 h1.02 r90
  text "P0.10" at 69.088,53.101 h1.02 r90
  text "P0.09" at 71.628,53.101 h1.02 r90
  text "P0.08" at 74.168,53.101 h1.02 r90
  text "P0.07" at 76.708,53.101 h1.02 r90
  text "P0.06" at 79.248,53.101 h1.02 r90
  text "P0.05" at 81.788,53.101 h1.02 r90
  text "P0.21" at 84.328,53.101 h1.02 r90
  text "P0.00" at 89.433,53.076 h1.02 r90
  text "P0.01" at 86.843,53.068 h1.02 r90
  text "R" at 7.383,52.758 h1.35 r90
  text "GPIO" at 72.111,45.516 h1.99 r90
  text "P0.13" at 74.6,45.392 h1.91 r90
  text "P0.14" at 77.292,45.392 h1.91 r90
  text "P0.15" at 79.985,45.392 h1.91 r90
  text "P0.16" at 82.677,45.392 h1.91 r90
  text "P0.17" at 85.369,45.392 h1.91 r90
  text "P0.18" at 88.062,45.392 h1.91 r90
  text "P0.19" at 90.754,45.392 h1.91 r90
  text "P0.20" at 93.447,45.392 h1.91 r90
  text "P0.21" at 96.139,45.341 h1.91 r90
  text "GPIO" at 24.114,41.891 h1.9 r90
  text "P0.00" at 27.775,41.773 h1.82 r90
  text "P0.01" at 32.914,41.773 h1.82 r90
  text "P0.05" at 36.768,41.773 h1.82 r90
  text "P0.06" at 39.338,41.773 h1.82 r90
  text "P0.07" at 41.908,41.773 h1.82 r90
  text "P0.08" at 44.477,41.773 h1.82 r90
  text "P0.09" at 47.871,41.773 h1.82 r90
  text "P0.10" at 52.235,41.773 h1.82 r90
  text "Function" at 72.111,40.046 h1.99 r90
  text "Button 1" at 74.6,39.728 h1.91 r90
  text "Button 2" at 77.292,39.728 h1.91 r90
  text "Button 3" at 79.985,39.728 h1.91 r90
  text "Button 4" at 82.677,39.728 h1.91 r90
  text "RESET" at 96.114,39.093 h1.91 r90
  text "LED 1" at 85.369,38.585 h1.91 r90
  text "LED 2" at 88.062,38.585 h1.91 r90
  text "LED 3" at 90.754,38.585 h1.91 r90
  text "LED 4" at 93.447,38.585 h1.91 r90
  text "Function" at 24.114,36.67 h1.9 r90
  text "NFC1" at 47.895,35.252 h1.82 r90
  text "NFC2" at 52.259,35.228 h1.82 r90
  text "XL1" at 27.775,34.912 h1.82 r90
  text "XL2" at 32.914,34.912 h1.82 r90
  text "RTS" at 36.768,34.912 h1.82 r90
  text "TXD" at 39.338,34.912 h1.82 r90
  text "CTS" at 41.908,34.912 h1.82 r90
  text "RXD" at 44.477,34.912 h1.82 r90
  text "SB17" at 96.139,31.93 h1.91 r90
  text "SB5" at 85.369,31.524 h1.91 r90
  text "SB6" at 88.062,31.524 h1.91 r90
  text "SB7" at 90.754,31.524 h1.91 r90
  text "SB8" at 93.447,31.524 h1.91 r90
  text "Short" at 72.111,30.97 h1.99 r90
  text "SB13/22" at 36.768,29.022 h1.82 r90
  text "SB14/23" at 39.338,29.022 h1.82 r90
  text "SB15/24" at 41.908,29.022 h1.82 r90
  text "SB16/25" at 44.477,29.022 h1.82 r90
  text "SB2" at 26.49,28.537 h1.82 r90
  text "SB4" at 29.06,28.537 h1.82 r90
  text "SB1" at 31.629,28.537 h1.82 r90
  text "SB3" at 34.199,28.537 h1.82 r90
  text "Short" at 24.114,28.008 h1.9 r90
  text "GPIO" at 95.656,24.818 h1.78 r90
  text "*" at 76.643,24.742 h2.54 r90
  text "*" at 92.34,24.742 h2.54 r90
  text "HW" at 72.111,22.334 h1.99 r90
  text "GPIO" at 31.913,22.064 h1.7 r90
  text "GPIO" at 43.889,22.064 h1.7 r90
  text "GPIO" at 53.319,22.079 h1.7 r90
  text "IF MCU" at 36.938,21.495 h1.7 r90
  text "PIN" at 46.593,19.97 h1.7 r90
  text "VDD" at 86.233,19.941 h1.78 r90
  text "HW" at 24.114,19.766 h1.9 r90
  text "PIN" at 95.662,19.177 h1.78 r90
  text "SB1x" at 41.665,19.058 h1.21 r90
  text "SB2x" at 40.065,18.84 h1.21 r90
  text "NFC" at 49.526,17.158 h1.7 r90
  text "mbed.org" at 14.986,17.043 h1.78 r90
  text "PIN" at 27.611,16.755 h1.7 r90
  text "PIN" at 43.889,16.755 h1.7 r90
  text "I/O EXPANDER" at 72.111,16.238 h1.99 r90
  text "(" at 75.641,16.157 h3.05 r90
  text "PIN" at 85.7,16.163 h1.78 r90
  text "P0.03 (A0)" at 51.181,13.957 h1.02 r90
  text "P0.04 (A1)" at 53.721,13.957 h1.02 r90
  text "P0.28 (A2)" at 56.261,13.957 h1.02 r90
  text "P0.29 (A3)" at 58.801,13.957 h1.02 r90
  text "P0.30 (A4)" at 61.335,13.957 h1.02 r90
  text "P0.31 (A5)" at 63.881,13.957 h1.02 r90
  text ")" at 75.641,13.109 h3.05 r90
  text "RESET" at 33.522,12.886 h1.02 r90
  text "nRF" at 91.008,12.601 h2.03 r90
  text "GND" at 41.142,12.073 h1.02 r90
  text "GND" at 43.605,12.073 h1.02 r90
  text "VDD" at 28.448,12.027 h1.02 r90
  text "VDD" at 30.988,12.027 h1.02 r90
  text "VDD" at 36.068,12.027 h1.02 r90
  text "N.C." at 46.272,11.877 h1.02 r90
  text "*" at 75.133,11.661 h2.54 r90
  text "5V" at 38.633,11.386 h1.02 r90
  text "EXP" at 84.531,11.077 h1.52 r90
  text "(" at 75.641,10.061 h3.05 r90
  text "I2C" at 87.325,9.299 h1.78 r90
  text "DETECT" at 80.721,8.537 h1.78 r90
  text ")" at 75.641,5.997 h3.05 r90
Mechanical 1:
  the board outline again, w0.254
Top Assembly:
  circle w0.1: c66.04,40.64 r1.6
  circle w0.1: c66.04,12.7 r1.6
  circle w0.1: c15.24,55.88 r1.6
  circle w0.1: c96.52,7.62 r1.6
  circle w0.1: c13.97,7.62 r1.6
Top Placement:
  lines w0.102: 36.982,16.358 38.514,16.358

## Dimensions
98.044,62.474 to 100.319,64.749 on Mechanical 3
98.069,-0.01 to 15.24,55.87 on Mechanical 3
98.069,-0.01 to 66.04,40.63 on Mechanical 3
98.069,-0.01 to 66.04,12.69 on Mechanical 3
98.069,-0.01 to 96.52,7.61 on Mechanical 3
98.069,-0.01 to 98.044,63.49 on Mechanical 3
0,1.006 to 96.52,7.61 on Mechanical 3
0,1.006 to 66.04,12.69 on Mechanical 3
0,1.006 to 15.24,55.87 on Mechanical 3
0,1.006 to 13.97,7.61 on Mechanical 3
0,1.006 to 101.6,10.15 on Mechanical 3
0,1.006 to 99.06,7.61 on Mechanical 3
